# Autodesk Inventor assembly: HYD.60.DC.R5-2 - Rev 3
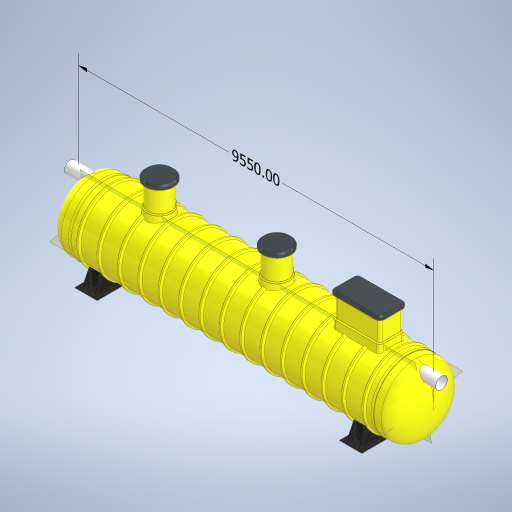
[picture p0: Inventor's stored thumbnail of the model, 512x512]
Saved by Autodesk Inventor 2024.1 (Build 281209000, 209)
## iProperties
Created: 2023-08
Part Number: HYD.60.DC.R5-2 - Rev 3
Document SubType Name: Assembly
Designer: macga
Author: macga
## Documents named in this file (42)
- D:\$ Protector Vault\Workspace\Automation Files\1. Protector Stardard Products\HydroProtectors\FAMILY\HYD.60 - Vernon\HYD.60.DC.R5-2 - Rev 3.iam
- D:\$ Protector Vault\Workspace\1. Protector Stardard Products\HydroProtectors\FAMILY\HORIZONTAL TANK - IPART\HORIZONTAL TANK - IPART.ipt
- D:\$ Protector Vault\Workspace\1. Protector Stardard Products\HydroProtectors\FAMILY\DOME - IPART\DOME - IPART\SU.DOME.1850-9.ipt
- D:\$ Protector Vault\Workspace\1. Protector Stardard Products\HydroProtectors\FAMILY\DOME - IPART\DOME - IPART.ipt
- D:\$ Protector Vault\Workspace\1. Protector Stardard Products\HydroProtectors\FAMILY\FOOT - IPART\FRP Foot - IPART\SU.HS.FOOT.1850.ipt
- D:\$ Protector Vault\Workspace\1. Protector Stardard Products\HydroProtectors\FAMILY\FOOT - IPART\FRP Foot - IPART.ipt
- D:\$ Protector Vault\Workspace\1. Protector Stardard Products\HydroProtectors\FAMILY\HYD.BAFFLE - IPART\SU.BAFFLE.1850\SU.BAFFLE.1850.ipt
- D:\$ Protector Vault\Workspace\1. Protector Stardard Products\HydroProtectors\FAMILY\HYD.BAFFLE - IPART\SU.BAFFLE.1850.ipt
- D:\$ Protector Vault\Workspace\1. Protector Stardard Products\HydroProtectors\FAMILY\ACD Base - IPART\SU.ACDBASE.1850\SU.ACDBASE.1850-300ACDFV.ipt
- D:\$ Protector Vault\Workspace\1. Protector Stardard Products\HydroProtectors\FAMILY\ACD Base - IPART\SU.ACDBASE.1850.ipt
- D:\$ Protector Vault\Workspace\1. Protector Stardard Products\HydroProtectors\FAMILY\ACDTUBE - IPART\ACDTUBE - IPART\ACDTUBE.300-1880.ipt
- D:\$ Protector Vault\Workspace\1. Protector Stardard Products\HydroProtectors\FAMILY\ACDTUBE - IPART\ACDTUBE - IPART.ipt
- D:\$ Protector Vault\Workspace\1. Protector Stardard Products\HydroProtectors\FAMILY\ACD FLOAT VALVE - IPART\ACD.FloatValve - IASSY\ACD.FVALVE.300.ASSY.iam
- D:\$ Protector Vault\Workspace\1. Protector Stardard Products\HydroProtectors\FAMILY\ACD FLOAT VALVE - IPART\ACD.FloatValve - IASSY.iam
- D:\$ Protector Vault\Workspace\Automation Files\1. Protector Stardard Products\HydroProtectors\FAMILY\CF.BASE - IPART\CF BASE DUAL - IPART\SU.CFBASE1.1850.DUAL\SU.CFBASE1.1850.DUAL-R5.300-OP.ipt
- D:\$ Protector Vault\Workspace\Automation Files\1. Protector Stardard Products\HydroProtectors\FAMILY\CF.BASE - IPART\CF BASE DUAL - IPART\SU.CFBASE1.1850.DUAL.ipt
- D:\$ Protector Vault\Workspace\1. Protector Stardard Products\HydroProtectors\FAMILY\COALESCER FILTER - IPART\CF-R5.iam
- D:\$ Protector Vault\Workspace\1. Protector Stardard Products\HydroProtectors\FAMILY\SU.600Dia Manway Adaptor - IPART\Horizontal 600mmDia Manway Adaptor (FLANGED) SU.MWA.HS.6R-1850-1850\SU.MWA.HS.6R-1850.ipt
- D:\$ Protector Vault\Workspace\1. Protector Stardard Products\HydroProtectors\FAMILY\SU.600Dia Manway Adaptor - IPART\SU.MWA.HS.6R - IPART.ipt
- D:\$ Protector Vault\Workspace\1. Protector Stardard Products\HydroProtectors\FAMILY\WIN.600mmDiaManwayRiser - IPART\600mmDia Manway Riser.ipt
- D:\$ Protector Vault\Workspace\1. Protector Stardard Products\HydroProtectors\Automation Files\600mmDia Manway Cover.ipt
- D:\$ Protector Vault\Workspace\1. Protector Stardard Products\HydroProtectors\HYD.50 300 Outlet Vertical.ipt
- D:\$ Protector Vault\Workspace\1. Protector Stardard Products\HydroProtectors\FAMILY\OUTLET ELBOW - IPART\OUTLET ELBOW - IPART.ipt
- D:\$ Protector Vault\Workspace\1. Protector Stardard Products\HydroProtectors\FAMILY\600x1200mm Manway Adaptor - IPART\600x1200mm Manway Adaptor - IPART\SU.MRADAPTOR.1850.600Lx1200W.ipt
- D:\$ Protector Vault\Workspace\1. Protector Stardard Products\HydroProtectors\FAMILY\600x1200mm Manway Adaptor - IPART\600x1200mm Manway Adaptor - IPART.ipt
- D:\$ Protector Vault\Workspace\1. Protector Stardard Products\HydroProtectors\Coalescer Guide Rail.ipt
- D:\$ Protector Vault\Workspace\1. Protector Stardard Products\HydroProtectors\ISO 4065 Pipe DN315x2.5xS63 - 1365.ipt
- D:\$ Protector Vault\Workspace\1. Protector Stardard Products\HydroProtectors\FAMILY\INLET PIPE ELBOW- IPART\INLET PIPE ELBOW- IPART\InletPipeElbow.300D.ipt
- D:\$ Protector Vault\Workspace\1. Protector Stardard Products\HydroProtectors\FAMILY\INLET PIPE ELBOW- IPART\INLET PIPE ELBOW- IPART.ipt
- D:\$ Protector Vault\Workspace\1. Protector Stardard Products\HydroProtectors\Automation Files\Access Risers\600x1200 Manway Riser.ipt
- D:\$ Protector Vault\Workspace\1. Protector Stardard Products\HydroProtectors\Automation Files\Access Risers\600x 1200mm Manway Cover.ipt
- D:\$ Protector Vault\Workspace\1. Protector Stardard Products\HydroProtectors\Upper Guide Rai Braket.ipt
- D:\$ Protector Vault\Workspace\1. Protector Stardard Products\Standard Components\Flanged Vent.ipt
- D:\$ Protector Vault\Workspace\1. Protector Stardard Products\HydroProtectors\HYD Oil Probe\Oil Probe Assembly.iam
- D:\$ Protector Vault\Workspace\1. Protector Stardard Products\Xtremeprotector\Vault\Chain.ipt
- D:\$ Protector Vault\Workspace\1. Protector Stardard Products\Xtremeprotector\Vault\Lifting Eye.ipt
- D:\$ Protector Vault\Workspace\1. Protector Stardard Products\HydroProtectors\FAMILY\OUTLET ELBOW - IPART\OUTLET ELBOW - IPART\OutletPipeElbow.300D-100DCoupling.ipt
- D:\$ Protector Vault\Workspace\1. Protector Stardard Products\Xtremeprotector\Vault\Chain\Chain-01.ipt
- D:\$ Protector Vault\Workspace\1. Protector Stardard Products\HydroProtectors\FAMILY\WIN.600mmDiaManwayRiser - IPART\600mmDia Manway Riser\SU.600mmDia.ManwayRiser.600-10.ipt
- D:\$ Protector Vault\Workspace\1. Protector Stardard Products\HydroProtectors\FAMILY\Coalescer Guide Rail-016.ipt
- D:\$ Protector Vault\Workspace\1. Protector Stardard Products\HydroProtectors\FAMILY\Coalescer Guide Rail-017.ipt
- D:\$ Protector Vault\Workspace\1. Protector Stardard Products\HydroProtectors\FAMILY\HORIZONTAL TANK - IPART\HORIZONTAL TANK - IPART\WIN.HB.1850x8200L-9.ipt
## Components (38 placed, 26 different names)
1. WIN.HB.1850x8200L-9:1
2. SU.DOME.1850-9:1 — Mate:1, Mate:3, Mate:10, Mate:78, Flush:14
3. SU.DOME.1850-9:2 — Mate:2, Mate:4, Mate:17, Mate:1, Angle:6
4. SU.HS.FOOT.1850:1 — Mate:5, Mate:6
5. SU.HS.FOOT.1850:2 — Mate:7, Mate:8
6. SU.BAFFLE.1850:1 — Mate:9, Mate:10, Mate:12
7. SU.ACDBASE.1850-300ACDFV:1 — Mate:11, Mate:12, Mate:13, Mate:14
8. ACDTUBE.300-1880:1 — Mate:13, Mate:14, Mate:15, Mate:38
9. ACD.FVALVE.300.ASSY:1 [sub-assembly] — Mate:15
10. SU.CFBASE1.1850.DUAL-R5.300-OP:1
11. CF-R5:1 [sub-assembly] — Mate:18, Mate:19, Mate:81, Tangent:3
12. CF-R5:2 [sub-assembly] — Mate:20, Mate:21, Mate:84, Tangent:4
13. SU.600mmDia.ManwayRiser.600-10:1 — Mate:30, Mate:31, Mate:40, Mate:41, Flush:2
14. SU.600mmDia.ManwayRiser.600-10:2 — Mate:32, Mate:33, Mate:44, Mate:45
15. 600mmDia Manway Cover:1 — Mate:32, Mate:33
16. 600mmDia Manway Cover:2 — Mate:30, Mate:31, Angle:2
17. HYD.50 300 Outlet Vertical:1 — Mate:34, Mate:35, Mate:36, Mate:37
18. OutletPipeElbow.300D-100DCoupling:2 — Mate:36, Mate:37, Mate:53, Mate:54, Angle:6
19. SU.MWA.HS.6R-1850:2 — Mate:38, Mate:39, Mate:40, Mate:41, Mate:68, Mate:69, Tangent:2, Flush:11, Mate:87
20. SU.MWA.HS.6R-1850:3 — Mate:43, Mate:44, Mate:45, Mate:66, Mate:67, Mate:87, Mate:73
21. Coalescer Guide Rail-016:1 — Mate:47, Mate:48, Mate:49, Mate:62, Mate:63, Flush:5
22. Coalescer Guide Rail-017:2 — Mate:50, Mate:51, Mate:52, Mate:64, Mate:65, Flush:6
23. ISO 4065 Pipe DN315x2.5xS63 - 1365:2 — Mate:78, Flush:14, Mate:79, Mate:80
24. ISO 4065 Pipe DN315x2.5xS63 - 1365:1 — Mate:53, Mate:54
25. InletPipeElbow.300D:1 — Mate:79, Mate:80
26. 600x1200 Manway Riser:1 — Flush:2, Mate:61, Flush:3, Flush:4, Flush:12, Flush:13, Mate:82, Mate:85
27. 600x 1200mm Manway Cover:1 — Mate:61, Flush:3, Flush:4, Angle:1
28. Upper Guide Rai Braket:1 — Mate:62, Mate:63, Flush:5
29. Upper Guide Rai Braket:2 — Mate:64, Mate:65, Flush:6
30. Flanged Vent:1 — Mate:66, Mate:67
31. Flanged Vent:2 — Mate:68, Mate:69
32. Flanged Vent:3 — Mate:76, Mate:77
33. SU.MRADAPTOR.1850.600Lx1200W:1 — Mate:70, Flush:7, Tangent:1, Flush:12, Flush:13, Mate:76, Mate:77
34. Oil Probe Assembly:1 [sub-assembly] — Flush:11, Mate:73, Angle:3
35. Chain-01:3 — Mate:81, Tangent:3, Mate:83
36. Chain-01:4 — Mate:84, Tangent:4, Mate:86
37. Lifting Eye:1 — Mate:82, Mate:83
38. Lifting Eye:2 — Mate:85, Mate:86
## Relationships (84: Mate 66, Flush 10, Angle 4, Tangent 4)
- Mate:1: SU.DOME.1850-9:1 ↔ SU.DOME.1850-9:2
- Mate:2: SU.DOME.1850-9:2
- Mate:3: SU.DOME.1850-9:1
- Mate:4: SU.DOME.1850-9:2
- Mate:5: SU.HS.FOOT.1850:1
- Mate:6: SU.HS.FOOT.1850:1
- Mate:7: SU.HS.FOOT.1850:2
- Mate:8: SU.HS.FOOT.1850:2
- Mate:9: SU.BAFFLE.1850:1
- Mate:10: SU.DOME.1850-9:1 ↔ SU.BAFFLE.1850:1
- Mate:11: SU.ACDBASE.1850-300ACDFV:1
- Mate:12: SU.BAFFLE.1850:1 ↔ SU.ACDBASE.1850-300ACDFV:1
- Mate:13: SU.ACDBASE.1850-300ACDFV:1 ↔ ACDTUBE.300-1880:1
- Mate:14: SU.ACDBASE.1850-300ACDFV:1 ↔ ACDTUBE.300-1880:1
- Mate:15: ACDTUBE.300-1880:1 ↔ ACD.FVALVE.300.ASSY:1
- Mate:17: SU.DOME.1850-9:2
- Mate:18: CF-R5:1
- Mate:19: CF-R5:1
- Mate:20: CF-R5:2
- Mate:21: CF-R5:2
- Mate:30: SU.600mmDia.ManwayRiser.600-10:1 ↔ 600mmDia Manway Cover:2
- Mate:31: SU.600mmDia.ManwayRiser.600-10:1 ↔ 600mmDia Manway Cover:2
- Mate:32: SU.600mmDia.ManwayRiser.600-10:2 ↔ 600mmDia Manway Cover:1
- Mate:33: SU.600mmDia.ManwayRiser.600-10:2 ↔ 600mmDia Manway Cover:1
- Mate:34: HYD.50 300 Outlet Vertical:1
- Mate:35: HYD.50 300 Outlet Vertical:1
- Mate:36: HYD.50 300 Outlet Vertical:1 ↔ OutletPipeElbow.300D-100DCoupling:2
- Mate:37: HYD.50 300 Outlet Vertical:1 ↔ OutletPipeElbow.300D-100DCoupling:2
- Mate:38: ACDTUBE.300-1880:1 ↔ SU.MWA.HS.6R-1850:2
- Mate:39: SU.MWA.HS.6R-1850:2
- Mate:40: SU.600mmDia.ManwayRiser.600-10:1 ↔ SU.MWA.HS.6R-1850:2
- Mate:41: SU.600mmDia.ManwayRiser.600-10:1 ↔ SU.MWA.HS.6R-1850:2
- Mate:43: SU.MWA.HS.6R-1850:3
- Mate:44: SU.600mmDia.ManwayRiser.600-10:2 ↔ SU.MWA.HS.6R-1850:3
- Mate:45: SU.600mmDia.ManwayRiser.600-10:2 ↔ SU.MWA.HS.6R-1850:3
- Mate:47: Coalescer Guide Rail-016:1
- Mate:48: Coalescer Guide Rail-016:1
- Mate:49: Coalescer Guide Rail-016:1
- Mate:50: Coalescer Guide Rail-017:2
- Mate:51: Coalescer Guide Rail-017:2
- Mate:52: Coalescer Guide Rail-017:2
- Mate:53: OutletPipeElbow.300D-100DCoupling:2 ↔ ISO 4065 Pipe DN315x2.5xS63 - 1365:1
- Mate:54: OutletPipeElbow.300D-100DCoupling:2 ↔ ISO 4065 Pipe DN315x2.5xS63 - 1365:1
- Flush:2: SU.600mmDia.ManwayRiser.600-10:1 ↔ 600x1200 Manway Riser:1
- Mate:61: 600x1200 Manway Riser:1 ↔ 600x 1200mm Manway Cover:1
- Flush:3: 600x1200 Manway Riser:1 ↔ 600x 1200mm Manway Cover:1
- Flush:4: 600x1200 Manway Riser:1 ↔ 600x 1200mm Manway Cover:1
- Mate:62: Coalescer Guide Rail-016:1 ↔ Upper Guide Rai Braket:1
- Mate:63: Coalescer Guide Rail-016:1 ↔ Upper Guide Rai Braket:1
- Flush:5: Coalescer Guide Rail-016:1 ↔ Upper Guide Rai Braket:1
- Mate:64: Coalescer Guide Rail-017:2 ↔ Upper Guide Rai Braket:2
- Mate:65: Coalescer Guide Rail-017:2 ↔ Upper Guide Rai Braket:2
- Flush:6: Coalescer Guide Rail-017:2 ↔ Upper Guide Rai Braket:2
- Mate:66: SU.MWA.HS.6R-1850:3 ↔ Flanged Vent:1
- Mate:67: SU.MWA.HS.6R-1850:3 ↔ Flanged Vent:1
- Mate:68: SU.MWA.HS.6R-1850:2 ↔ Flanged Vent:2
- Mate:69: SU.MWA.HS.6R-1850:2 ↔ Flanged Vent:2
- Mate:70: SU.MRADAPTOR.1850.600Lx1200W:1
- Flush:7: SU.MRADAPTOR.1850.600Lx1200W:1
- Angle:1: 600x 1200mm Manway Cover:1
- Tangent:1: SU.MRADAPTOR.1850.600Lx1200W:1
- Angle:2: 600mmDia Manway Cover:2
- Tangent:2: SU.MWA.HS.6R-1850:2
- Flush:11: SU.MWA.HS.6R-1850:2 ↔ Oil Probe Assembly:1
- Mate:73: SU.MWA.HS.6R-1850:3 ↔ Oil Probe Assembly:1
- Angle:3: Oil Probe Assembly:1
- Flush:12: 600x1200 Manway Riser:1 ↔ SU.MRADAPTOR.1850.600Lx1200W:1
- Flush:13: 600x1200 Manway Riser:1 ↔ SU.MRADAPTOR.1850.600Lx1200W:1
- Mate:76: Flanged Vent:3 ↔ SU.MRADAPTOR.1850.600Lx1200W:1
- Mate:77: Flanged Vent:3 ↔ SU.MRADAPTOR.1850.600Lx1200W:1
- Mate:78: SU.DOME.1850-9:1 ↔ ISO 4065 Pipe DN315x2.5xS63 - 1365:2
- Flush:14: SU.DOME.1850-9:1 ↔ ISO 4065 Pipe DN315x2.5xS63 - 1365:2
- Mate:79: ISO 4065 Pipe DN315x2.5xS63 - 1365:2 ↔ InletPipeElbow.300D:1
- Mate:80: ISO 4065 Pipe DN315x2.5xS63 - 1365:2 ↔ InletPipeElbow.300D:1
- Angle:6: SU.DOME.1850-9:2 ↔ OutletPipeElbow.300D-100DCoupling:2
- Mate:81: CF-R5:1 ↔ Chain-01:3
- Tangent:3: CF-R5:1 ↔ Chain-01:3
- Mate:82: 600x1200 Manway Riser:1 ↔ Lifting Eye:1
- Mate:83: Chain-01:3 ↔ Lifting Eye:1
- Mate:84: CF-R5:2 ↔ Chain-01:4
- Tangent:4: CF-R5:2 ↔ Chain-01:4
- Mate:85: 600x1200 Manway Riser:1 ↔ Lifting Eye:2
- Mate:86: Chain-01:4 ↔ Lifting Eye:2
- Mate:87: SU.MWA.HS.6R-1850:2 ↔ SU.MWA.HS.6R-1850:3
